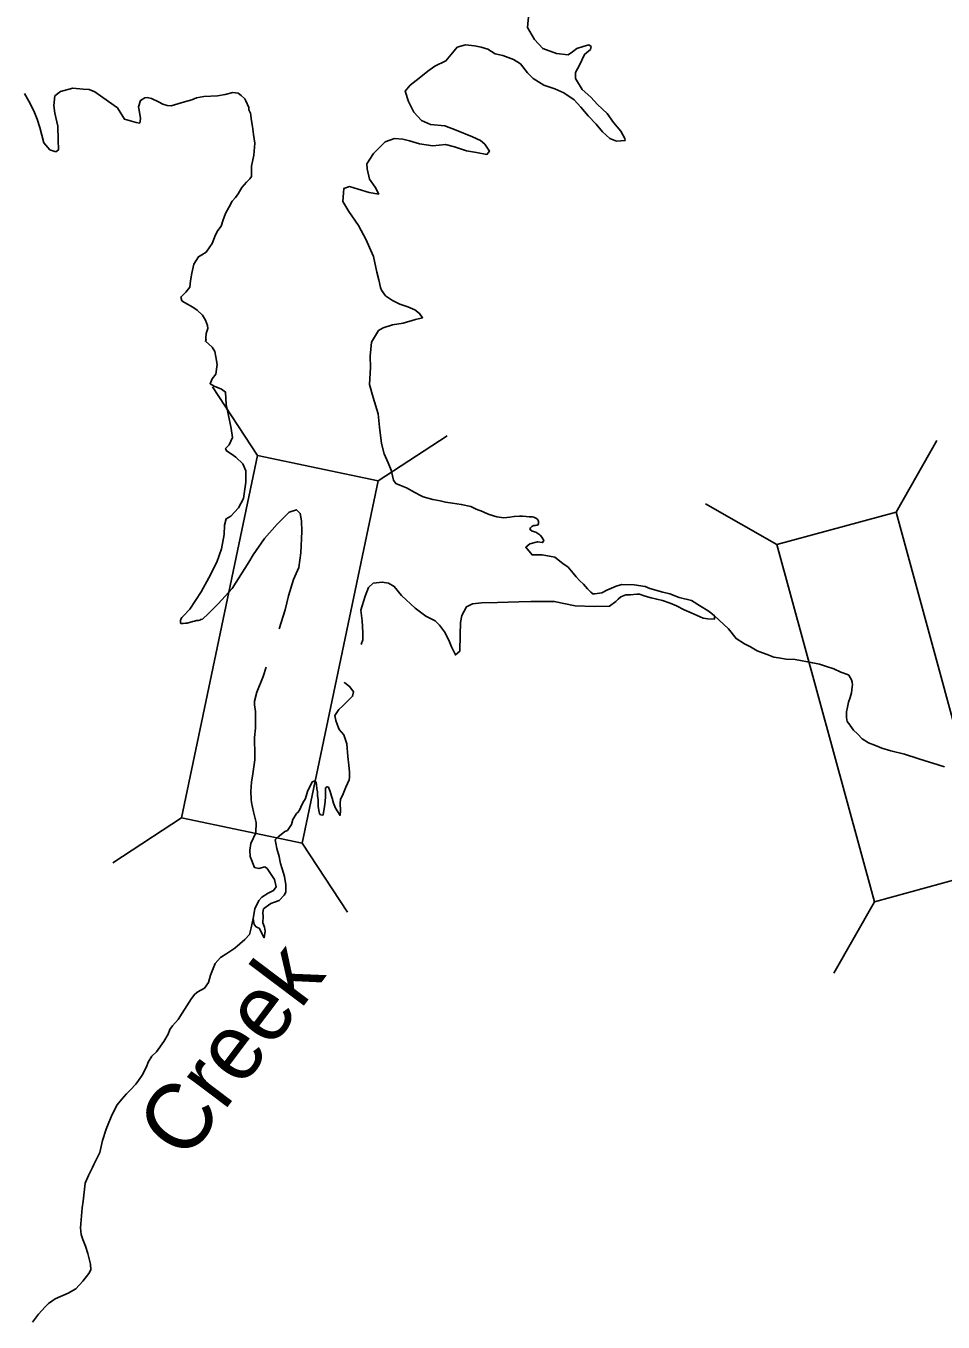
# Model space of a CAD drawing. Extents: x -492261 to -432772, y 1441225 to 1452922.
# Drawn here: x -461497 to -461423.4, y 1451924 to 1452028 of the extents above; entities that cross this region are included whole.
import ezdxf

# ---------------------------------------------------------------- set-up
doc = ezdxf.new("R2010")
doc.units = 0
doc.layers.add('Default', color=7, linetype='Continuous')

msp = doc.modelspace()

# ---------------------------------------------------------------- linework, layer by layer
at = {"layer": 'Default'}
for p, q in [((-461478.39, 1451993.5), (-461482, 1451999.02)), ((-461468.7, 1451991.47), (-461463.18, 1451995.08)), ((-461427.17, 1451988.97), (-461423.89, 1451994.7)), ((-461436.72, 1451986.36), (-461442.45, 1451989.64)), ((-461484.48, 1451964.43), (-461490, 1451960.82)), ((-461474.79, 1451962.4), (-461471.18, 1451956.87)), ((-461428.9, 1451957.71), (-461432.17, 1451951.98))]:
    msp.add_line(p, q, dxfattribs=at)
for points in [[(-461456.63, 1452028.98), (-461456.74, 1452027.85), (-461456.18, 1452026.88), (-461455.49, 1452026.16), (-461454.41, 1452025.75), (-461453.48, 1452025.66), (-461453.11, 1452025.89), (-461452.76, 1452026.15), (-461452.26, 1452026.33), (-461451.81, 1452026.44), (-461451.63, 1452026.31), (-461451.68, 1452026.09), (-461452.15, 1452025.68), (-461452.57, 1452024.82), (-461452.88, 1452024.24), (-461452.88, 1452023.74), (-461452.34, 1452022.87), (-461451.66, 1452022.25), (-461451.12, 1452021.66), (-461450.34, 1452020.94), (-461449.82, 1452020.22), (-461449.24, 1452019.53), (-461448.91, 1452018.93), (-461448.9, 1452018.78), (-461449.58, 1452018.72), (-461450.13, 1452018.94), (-461450.72, 1452019.46), (-461451.23, 1452020.1), (-461451.86, 1452020.75), (-461452.45, 1452021.44), (-461452.98, 1452022.04), (-461453.81, 1452022.6), (-461454.54, 1452022.92), (-461455.43, 1452023.23), (-461456.28, 1452023.74), (-461456.72, 1452024.21), (-461457.3, 1452024.93), (-461457.86, 1452025.28), (-461458.71, 1452025.59), (-461459.32, 1452025.73), (-461459.9, 1452026.1), (-461460.45, 1452026.27), (-461460.98, 1452026.36), (-461461.71, 1452026.45), (-461462.36, 1452026.27), (-461462.6, 1452025.96), (-461463.27, 1452025.18), (-461464.16, 1452024.74), (-461464.73, 1452024.33), (-461465.43, 1452023.77), (-461466.15, 1452023.21), (-461466.54, 1452022.73), (-461466.28, 1452021.9), (-461465.84, 1452021.06), (-461465.23, 1452020.37), (-461464.5, 1452020.05), (-461463.37, 1452019.96), (-461462.44, 1452019.6), (-461461.13, 1452019.07), (-461460.5, 1452018.78), (-461460.15, 1452018.48), (-461459.79, 1452017.91), (-461459.99, 1452017.66), (-461460.82, 1452017.82)], [(-461494.56, 1452017.86), (-461495.04, 1452018.03), (-461495.52, 1452018.6), (-461495.84, 1452019.83), (-461496.07, 1452020.5), (-461496.33, 1452021.15), (-461496.74, 1452021.94), (-461497.08, 1452022.54)], [(-461480.38, 1451994.95), (-461480.51, 1451995.68), (-461480.73, 1451996.85), (-461480.89, 1451997.6), (-461480.95, 1451998.6), (-461481.28, 1451998.83), (-461481.86, 1451999.07), (-461482.19, 1451999.26), (-461482.02, 1451999.67), (-461481.72, 1452000.02), (-461481.61, 1452000.8), (-461481.74, 1452001.42), (-461481.82, 1452001.85), (-461482.03, 1452002.2), (-461482.56, 1452002.67), (-461482.51, 1452002.77), (-461482.54, 1452002.84), (-461482.54, 1452002.94), (-461482.49, 1452003.29), (-461482.37, 1452003.7), (-461482.4, 1452003.95), (-461482.56, 1452004.37), (-461482.81, 1452004.77), (-461483.22, 1452005.16), (-461483.57, 1452005.41), (-461484.25, 1452005.78), (-461484.46, 1452005.92), (-461484.54, 1452006.22), (-461484.44, 1452006.32), (-461484.14, 1452006.6), (-461483.82, 1452007.01), (-461483.75, 1452007.51), (-461483.66, 1452008.14), (-461483.49, 1452008.87), (-461483.13, 1452009.45), (-461482.85, 1452009.6), (-461482.5, 1452009.83), (-461482.21, 1452010.24), (-461482.01, 1452010.52), (-461481.75, 1452011.22), (-461481.58, 1452011.55), (-461481.3, 1452011.9), (-461481.14, 1452012.41), (-461480.94, 1452012.91), (-461480.65, 1452013.47), (-461480.43, 1452013.92), (-461480.16, 1452014.2), (-461479.94, 1452014.5), (-461479.64, 1452015.01), (-461479.27, 1452015.44), (-461479, 1452015.69), (-461478.88, 1452015.9), (-461478.86, 1452016.72), (-461478.67, 1452017.6), (-461478.61, 1452018.56), (-461478.7, 1452019.26), (-461478.78, 1452019.91), (-461478.86, 1452020.36), (-461478.94, 1452020.96), (-461479.07, 1452021.23), (-461479.08, 1452021.43), (-461479.33, 1452021.95), (-461479.41, 1452022.13), (-461479.69, 1452022.4), (-461479.94, 1452022.57), (-461480.37, 1452022.62), (-461480.97, 1452022.46), (-461481.59, 1452022.37), (-461482.69, 1452022.31), (-461483.27, 1452022.2), (-461483.64, 1452022.05), (-461484.24, 1452021.89), (-461484.77, 1452021.73), (-461485.32, 1452021.57), (-461485.64, 1452021.59), (-461485.97, 1452021.69), (-461486.32, 1452021.88), (-461486.88, 1452022.15), (-461487.23, 1452022.22), (-461487.43, 1452022.19), (-461487.78, 1452021.99), (-461487.94, 1452021.49), (-461487.89, 1452021.21), (-461487.78, 1452020.54), (-461487.83, 1452020.18), (-461488.13, 1452020.21), (-461489.06, 1452020.49), (-461489.62, 1452021.39), (-461490.33, 1452021.9), (-461491.42, 1452022.69), (-461491.9, 1452022.86), (-461492.37, 1452022.9), (-461493.2, 1452022.97), (-461494.2, 1452022.7), (-461494.64, 1452022.35), (-461494.73, 1452021.59), (-461494.63, 1452020.97), (-461494.39, 1452019.92), (-461494.37, 1452018.82), (-461494.36, 1452018.02), (-461494.56, 1452017.86)], [(-461460.82, 1452017.82), (-461461.62, 1452017.96), (-461462.58, 1452018.27), (-461463.3, 1452018.46), (-461464.33, 1452018.35), (-461465.38, 1452018.51), (-461466.19, 1452018.75), (-461466.74, 1452018.89), (-461467.39, 1452018.93), (-461468.14, 1452018.67), (-461469.08, 1452017.73), (-461469.62, 1452016.9), (-461469.59, 1452016.5), (-461469.4, 1452015.67), (-461468.95, 1452015.03), (-461468.66, 1452014.48), (-461469.44, 1452014.6), (-461470.3, 1452014.88), (-461471, 1452015.08), (-461471.45, 1452014.94), (-461471.54, 1452013.89), (-461471.07, 1452013.07), (-461470.28, 1452011.95), (-461469.67, 1452010.81), (-461469.41, 1452010.19), (-461469.07, 1452009.46), (-461468.81, 1452008.21), (-461468.65, 1452007.59), (-461468.51, 1452006.99), (-461468.44, 1452006.77), (-461468.13, 1452006.32), (-461467.57, 1452005.93), (-461466.97, 1452005.66), (-461466.34, 1452005.44), (-461465.76, 1452005.2), (-461465.38, 1452004.9), (-461465.15, 1452004.56), (-461465.72, 1452004.42), (-461466.7, 1452004.13), (-461467.57, 1452004), (-461468.3, 1452003.74), (-461468.69, 1452003.53), (-461469.23, 1452002.6), (-461469.34, 1452001.47), (-461469.31, 1452000.57), (-461469.39, 1451999.21), (-461469.1, 1451998.16), (-461468.71, 1451996.84), (-461468.59, 1451995.79), (-461468.45, 1451994.46), (-461468.23, 1451993.65)], [(-461484.37, 1451980.58), (-461483.8, 1451981.18), (-461482.9, 1451982.57), (-461482.28, 1451983.7), (-461481.65, 1451984.96), (-461481.26, 1451986.02), (-461481.05, 1451987.18), (-461481.04, 1451987.93), (-461480.89, 1451988.43), (-461480.52, 1451988.64), (-461479.9, 1451989.3), (-461479.51, 1451990.05), (-461479.33, 1451991.38), (-461479.32, 1451992.29), (-461479.57, 1451992.83), (-461480.13, 1451993.38), (-461480.51, 1451993.65), (-461480.87, 1451993.87), (-461480.94, 1451994.07), (-461480.67, 1451994.37), (-461480.38, 1451994.95)], [(-461456.53, 1451987.63), (-461456.5, 1451987.71), (-461456.39, 1451987.8), (-461456.21, 1451987.89), (-461456.11, 1451987.89), (-461456.02, 1451987.91), (-461455.95, 1451987.93), (-461455.89, 1451987.96), (-461455.86, 1451988.03), (-461455.84, 1451988.1), (-461455.86, 1451988.21), (-461455.87, 1451988.3), (-461455.93, 1451988.39), (-461456.05, 1451988.49), (-461456.21, 1451988.57), (-461456.34, 1451988.58), (-461456.59, 1451988.58), (-461456.83, 1451988.62), (-461457.12, 1451988.64), (-461457.38, 1451988.64), (-461457.81, 1451988.62), (-461458.15, 1451988.57), (-461458.63, 1451988.51), (-461459.2, 1451988.6), (-461459.8, 1451988.78), (-461460.17, 1451988.94), (-461460.33, 1451989.01), (-461460.85, 1451989.2), (-461461.27, 1451989.42), (-461462.04, 1451989.58), (-461462.75, 1451989.68), (-461463.3, 1451989.77), (-461463.74, 1451989.86), (-461464.31, 1451989.97), (-461465.11, 1451990.18), (-461465.27, 1451990.27), (-461465.77, 1451990.55), (-461466.44, 1451990.91), (-461466.96, 1451991.14), (-461467.3, 1451991.26), (-461467.49, 1451991.53), (-461467.56, 1451991.87), (-461467.67, 1451992.33), (-461467.9, 1451992.93), (-461468.23, 1451993.65)], [(-461476.65, 1451979.6), (-461476.16, 1451981.13), (-461475.9, 1451982.24), (-461475.49, 1451983.57), (-461475.08, 1451984.53), (-461474.92, 1451985.71), (-461474.84, 1451987.41), (-461474.85, 1451988.26), (-461474.96, 1451988.86), (-461475.27, 1451989.16), (-461475.84, 1451988.95), (-461476.81, 1451987.99), (-461477.82, 1451986.85), (-461478.73, 1451985.55), (-461479.09, 1451984.95), (-461480.42, 1451982.83), (-461481.53, 1451981.61), (-461482.42, 1451980.74), (-461482.68, 1451980.49)], [(-461456.53, 1451987.63), (-461456.51, 1451987.56), (-461456.36, 1451987.44), (-461456.05, 1451987.37), (-461455.73, 1451987.14), (-461455.7, 1451987.09), (-461455.57, 1451986.97), (-461455.42, 1451986.7), (-461455.52, 1451986.52), (-461455.92, 1451986.59), (-461456.54, 1451986.43), (-461456.87, 1451986.15), (-461456.36, 1451985.53), (-461455.55, 1451985.54), (-461454.53, 1451985.36), (-461453.89, 1451984.84), (-461453.46, 1451984.54), (-461453.06, 1451984.07), (-461452.83, 1451983.78), (-461452.52, 1451983.45), (-461452.24, 1451983.18), (-461451.91, 1451982.81), (-461451.66, 1451982.54), (-461451.48, 1451982.42), (-461451.33, 1451982.42), (-461450.78, 1451982.5), (-461450.36, 1451982.71), (-461449.61, 1451983.02), (-461449.16, 1451983.17), (-461448.18, 1451983.14), (-461447.28, 1451983), (-461446.93, 1451982.85), (-461445.87, 1451982.54), (-461445.32, 1451982.4), (-461444.56, 1451982.13), (-461443.58, 1451981.87), (-461442.85, 1451981.41), (-461442.24, 1451981.06), (-461442.02, 1451980.89), (-461441.74, 1451980.64), (-461441.73, 1451980.39), (-461442.26, 1451980.41), (-461442.64, 1451980.46), (-461443.59, 1451980.89), (-461444.17, 1451981.14), (-461444.78, 1451981.45), (-461445.28, 1451981.65), (-461445.89, 1451981.87), (-461446.36, 1451981.98), (-461446.82, 1451982.1), (-461447.29, 1451982.22), (-461447.75, 1451982.39), (-461447.97, 1451982.39), (-461448.47, 1451982.33), (-461448.7, 1451982.33), (-461448.85, 1451982.33), (-461449.25, 1451982.17), (-461449.47, 1451981.99), (-461449.64, 1451981.79), (-461450.14, 1451981.43), (-461451.37, 1451981.39), (-461452.9, 1451981.44), (-461454.58, 1451981.8), (-461456.46, 1451981.8), (-461457.43, 1451981.78), (-461459.14, 1451981.71), (-461460.41, 1451981.69), (-461461.14, 1451981.61), (-461461.61, 1451981.38), (-461462, 1451980.67), (-461462.1, 1451980.12), (-461462.13, 1451979.11), (-461462.17, 1451977.81), (-461462.51, 1451977.51), (-461462.82, 1451978.15), (-461463.03, 1451978.7), (-461463.39, 1451979.37), (-461463.8, 1451979.89), (-461464.13, 1451980.24), (-461464.88, 1451980.63), (-461465.74, 1451981.25), (-461466.83, 1451982.28), (-461467.42, 1451983), (-461467.87, 1451983.27), (-461468.38, 1451983.36), (-461469.1, 1451983.28), (-461469.47, 1451982.92)], [(-461469.47, 1451982.92), (-461469.76, 1451982.22), (-461470.1, 1451981.09), (-461469.99, 1451980.24), (-461469.95, 1451979.31), (-461469.94, 1451978.71), (-461470.08, 1451978.35)], [(-461482.68, 1451980.49), (-461482.79, 1451980.39), (-461482.93, 1451980.34), (-461483.01, 1451980.31), (-461483.13, 1451980.28), (-461483.27, 1451980.26), (-461483.43, 1451980.23), (-461483.58, 1451980.18), (-461484.03, 1451980.07), (-461484.16, 1451980.05), (-461484.36, 1451980.03), (-461484.51, 1451980.03), (-461484.55, 1451980.06), (-461484.57, 1451980.12), (-461484.57, 1451980.17), (-461484.57, 1451980.24), (-461484.55, 1451980.31), (-461484.53, 1451980.36), (-461484.5, 1451980.43), (-461484.45, 1451980.5), (-461484.37, 1451980.58)], [(-461441.74, 1451980.64), (-461440.6, 1451979.6), (-461440, 1451978.82), (-461439.32, 1451978.4), (-461438.85, 1451978.17), (-461438.32, 1451977.84), (-461437.87, 1451977.69), (-461437.5, 1451977.54), (-461436.97, 1451977.34), (-461436.6, 1451977.29), (-461435.97, 1451977.17), (-461435.25, 1451977.14), (-461433.85, 1451976.87), (-461433.32, 1451976.77), (-461432.82, 1451976.62), (-461432.17, 1451976.39), (-461431.59, 1451976.14), (-461431.07, 1451975.94), (-461430.96, 1451975.9)], [(-461476.42, 1451960.35), (-461476.23, 1451959.73), (-461476.12, 1451959.08), (-461476.12, 1451958.5), (-461476.11, 1451958.48), (-461476.26, 1451958.23), (-461476.66, 1451957.82), (-461477.03, 1451957.69), (-461477.31, 1451957.56), (-461477.68, 1451957.31), (-461477.9, 1451957.13), (-461477.95, 1451956.85), (-461477.97, 1451956.8), (-461477.94, 1451956.55), (-461477.96, 1451956.02), (-461477.83, 1451955.67), (-461477.78, 1451955.35), (-461477.85, 1451954.82), (-461478.26, 1451955.59), (-461478.46, 1451955.67), (-461478.66, 1451955.89), (-461478.74, 1451956.36), (-461478.6, 1451957.14), (-461478.29, 1451957.82), (-461478.04, 1451958.08), (-461477.54, 1451958.41), (-461477.09, 1451958.62), (-461476.9, 1451958.92), (-461477.03, 1451959.49), (-461477.39, 1451960.07), (-461477.62, 1451960.39), (-461477.8, 1451960.51), (-461478.27, 1451960.38), (-461478.62, 1451960.45), (-461478.98, 1451961.35), (-461478.99, 1451961.85), (-461478.92, 1451962.38), (-461478.51, 1451963.23), (-461478.49, 1451964.06), (-461478.71, 1451964.93), (-461478.87, 1451965.66), (-461478.89, 1451965.93), (-461478.93, 1451966.56), (-461478.86, 1451967.31), (-461478.77, 1451967.96), (-461478.61, 1451969.09), (-461478.6, 1451969.9), (-461478.63, 1451970.42), (-461478.63, 1451970.9), (-461478.54, 1451971.63), (-461478.55, 1451972.08), (-461478.54, 1451972.98), (-461478.62, 1451973.5), (-461478.62, 1451973.8), (-461478.43, 1451974.51), (-461477.92, 1451975.79), (-461477.7, 1451976.52)], [(-461430.87, 1451971.9), (-461431.08, 1451972.17), (-461431.13, 1451972.5), (-461431.13, 1451972.61), (-461431.13, 1451972.94), (-461431.05, 1451973.33), (-461430.97, 1451973.71), (-461430.86, 1451974.1), (-461430.75, 1451974.46), (-461430.72, 1451974.71), (-461430.69, 1451974.96), (-461430.66, 1451975.12), (-461430.69, 1451975.32), (-461430.75, 1451975.51), (-461430.96, 1451975.9)], [(-461471.42, 1451975.32), (-461471.4, 1451975.31), (-461470.97, 1451974.96), (-461470.69, 1451974.54), (-461470.76, 1451974.19), (-461471.21, 1451973.76), (-461471.53, 1451973.42), (-461471.87, 1451973.12), (-461472.19, 1451972.66), (-461472.11, 1451972.24), (-461471.98, 1451971.87), (-461471.83, 1451971.54), (-461471.45, 1451971.1), (-461471.21, 1451970.37), (-461471.15, 1451969.35), (-461471.06, 1451968.67), (-461471.01, 1451968.1), (-461471, 1451967.67), (-461471.02, 1451967.49), (-461471.29, 1451966.91), (-461471.46, 1451966.51), (-461471.58, 1451966.23), (-461471.73, 1451965.93), (-461471.75, 1451965.6), (-461471.72, 1451965.03), (-461471.76, 1451964.63), (-461472.12, 1451965.22), (-461472.28, 1451965.62), (-461472.41, 1451966.02), (-461472.46, 1451966.17), (-461472.56, 1451966.55), (-461472.67, 1451966.82), (-461472.69, 1451966.89), (-461472.79, 1451966.94), (-461472.94, 1451966.84), (-461472.94, 1451966.72), (-461472.93, 1451966.16), (-461472.95, 1451965.76), (-461473.02, 1451965.34), (-461473.07, 1451965.01), (-461473.12, 1451964.71), (-461473.14, 1451964.66), (-461473.32, 1451964.68), (-461473.42, 1451964.78), (-461473.44, 1451964.9), (-461473.53, 1451965.35), (-461473.53, 1451965.88), (-461473.56, 1451966.23), (-461473.56, 1451966.36), (-461473.57, 1451966.53), (-461473.62, 1451966.76), (-461473.65, 1451967.08), (-461473.68, 1451967.28), (-461473.8, 1451967.41), (-461474, 1451967.33), (-461474.37, 1451966.55), (-461474.54, 1451965.99), (-461474.76, 1451965.64), (-461474.9, 1451965.31), (-461475, 1451965.11), (-461475.12, 1451964.91), (-461475.25, 1451964.78), (-461475.54, 1451964.3), (-461475.66, 1451963.92), (-461475.98, 1451963.42), (-461476.2, 1451963.34), (-461476.5, 1451963.11), (-461476.72, 1451962.91), (-461476.97, 1451962.68), (-461476.92, 1451962.4), (-461476.84, 1451961.98), (-461476.65, 1451961.33), (-461476.57, 1451960.88), (-461476.55, 1451960.78), (-461476.42, 1451960.35)], [(-461430.87, 1451971.9), (-461430.84, 1451971.84), (-461430.57, 1451971.47), (-461430.27, 1451971.17), (-461429.89, 1451970.79), (-461429.37, 1451970.47), (-461428.82, 1451970.24), (-461428.32, 1451970.04), (-461427.59, 1451969.81), (-461426.49, 1451969.56), (-461425.42, 1451969.19), (-461424.84, 1451969.01), (-461424.22, 1451968.84), (-461423.27, 1451968.54)], [(-461478.74, 1451956.36), (-461478.89, 1451955.63), (-461479.04, 1451955.08), (-461479.39, 1451954.68), (-461480.2, 1451953.98), (-461480.85, 1451953.55), (-461481.35, 1451953.25), (-461481.77, 1451952.77), (-461482.15, 1451951.82), (-461482.32, 1451951.22), (-461482.65, 1451950.77), (-461483.17, 1451950.49), (-461483.4, 1451950.29), (-461483.67, 1451949.94), (-461484.42, 1451948.77), (-461484.75, 1451948.26), (-461485.2, 1451947.76), (-461485.43, 1451947.46), (-461485.55, 1451947.09), (-461485.9, 1451946.49), (-461486.5, 1451945.68), (-461486.85, 1451945.33), (-461487.15, 1451944.83), (-461487.3, 1451944.46), (-461487.63, 1451943.81), (-461487.93, 1451943.38), (-461488.15, 1451943.08), (-461488.58, 1451942.63), (-461488.88, 1451942.3), (-461489.28, 1451941.88), (-461489.63, 1451941.43), (-461490.03, 1451940.65), (-461490.31, 1451940), (-461490.53, 1451939.47), (-461490.83, 1451938.57), (-461491.03, 1451937.59), (-461491.51, 1451936.62), (-461491.61, 1451936.39), (-461491.93, 1451935.74), (-461492.21, 1451935.14), (-461492.38, 1451933.69), (-461492.46, 1451933.16), (-461492.51, 1451932.51), (-461492.59, 1451931.56), (-461492.54, 1451931.03), (-461492.39, 1451930.61), (-461492.19, 1451930.08), (-461491.99, 1451929.48), (-461491.79, 1451928.63), (-461491.76, 1451928.18), (-461491.91, 1451927.9), (-461492.39, 1451927.27), (-461492.96, 1451926.67), (-461493.56, 1451926.3), (-461494.61, 1451925.85), (-461494.89, 1451925.67), (-461495.16, 1451925.47), (-461495.41, 1451925.22), (-461495.94, 1451924.64), (-461496.43, 1451923.99)]]:
    msp.add_lwpolyline(points, dxfattribs=at)
for points in [[(-461478.39, 1451993.5), (-461484.48, 1451964.43), (-461474.79, 1451962.4), (-461468.7, 1451991.47)], [(-461436.72, 1451986.36), (-461428.9, 1451957.71), (-461419.35, 1451960.32), (-461427.17, 1451988.97)]]:
    msp.add_lwpolyline(points, close=True, dxfattribs=at)

# ---------------------------------------------------------------- texts
msp.add_text('Creek', height=5.28, rotation=53, dxfattribs=at).set_placement((-461484.16, 1451936.77))

doc.saveas('drawing.dxf')
